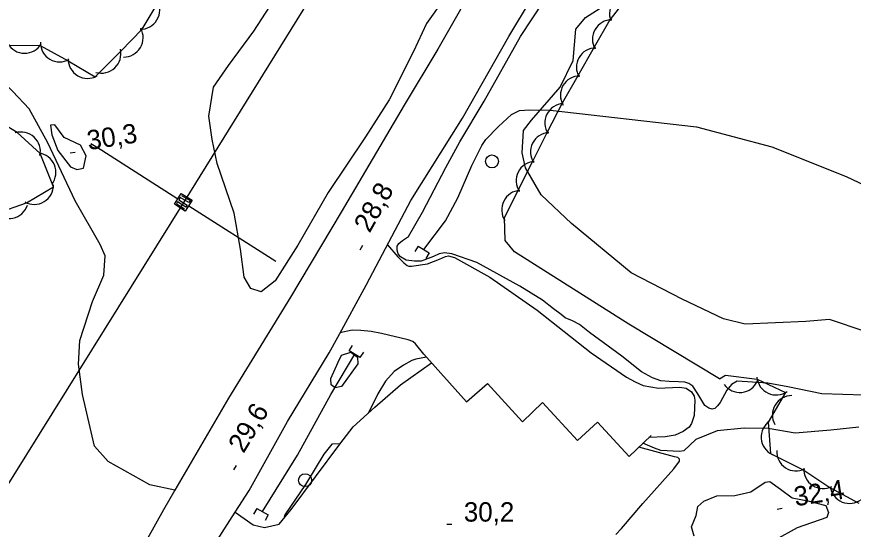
# Model space of a CAD drawing. Extents: x 646142 to 649934, y 5874075 to 5876351.
# Drawn here: x 648161.2 to 648290.8, y 5875445.6 to 5875524.9 of the extents above; entities that cross this region are included whole.
import ezdxf

# ---------------------------------------------------------------- set-up
doc = ezdxf.new("R2010")
doc.units = 0
for name, color, linetype in [('Niveau 1', 7, 'Continuous'), ('Niveau 19', 7, 'Continuous'), ('Niveau 2', 7, 'Continuous'), ('Niveau 21', 7, 'Continuous'), ('Niveau 22', 7, 'Continuous'), ('Niveau 26', 7, 'Continuous'), ('Niveau 3', 7, 'Continuous'), ('Niveau 36', 7, 'Continuous'), ('Niveau 37', 7, 'Continuous'), ('Niveau 4', 7, 'Continuous'), ('Niveau 44', 7, 'Continuous')]:
    doc.layers.add(name, color=color, linetype=linetype)

msp = doc.modelspace()

# ---------------------------------------------------------------- linework, layer by layer
at = {"layer": 'Niveau 1'}
for points in [[(648171.58, 5875501.45), (648172.01, 5875503.38), (648171.14, 5875505.04), (648168.58, 5875506.22), (648167.17, 5875508.17), (648166.49, 5875508.12), (648166.66, 5875506.64), (648167.59, 5875504.18), (648169.56, 5875501.69), (648170.56, 5875501.26), (648171.58, 5875501.45)], [(648224.69, 5875472.21), (648223.04, 5875471.91), (648222.42, 5875471.68), (648221.14, 5875470.99), (648219.67, 5875469.97), (648218.33, 5875468.52), (648217.17, 5875466.55), (648215.68, 5875463.51)], [(648291.63, 5875461.36), (648287.32, 5875460.9), (648281.8, 5875460.46), (648277.63, 5875461.15), (648273.91, 5875461.2), (648269.7, 5875460.8), (648266.43, 5875459.45), (648264.56, 5875457.69), (648263.9, 5875457.63)], [(648211.31, 5875458.79), (648210.02, 5875458.75), (648208.81, 5875457.22), (648205.96, 5875452.5), (648202.76, 5875447.82), (648202.6, 5875447.26)], [(648263.9, 5875457.63), (648261.01, 5875457.78), (648259.99, 5875458.12), (648258.21, 5875458.88)]]:
    msp.add_lwpolyline(points, dxfattribs=at)
at = {"layer": 'Niveau 19'}
for points in [[(648218.66, 5875489.6), (648220.25, 5875487.76), (648221.18, 5875486.8), (648221.73, 5875486.37), (648221.95, 5875486.31), (648222.39, 5875486.29), (648224.86, 5875486.63), (648226.71, 5875487.39), (648227.65, 5875487.78), (648228.12, 5875487.87), (648229.05, 5875487.61), (648234.53, 5875484.58), (648241.81, 5875479.48), (648250.2, 5875472.9), (648255.66, 5875469.11), (648257, 5875468.38), (648258.25, 5875467.82), (648260.62, 5875467.4), (648261.64, 5875467.44), (648263.92, 5875467.58), (648264.89, 5875467.4), (648265.72, 5875466.84), (648266.14, 5875466.18), (648266.24, 5875465.54), (648266.14, 5875463.19), (648265.75, 5875461.93), (648265.39, 5875461.38), (648264.45, 5875460.73), (648263.19, 5875460.14), (648261.64, 5875459.88), (648259.13, 5875459.77)], [(648224.29, 5875472.66), (648223.02, 5875474.25), (648222.56, 5875474.65), (648221.84, 5875474.87), (648217.72, 5875475.87), (648216.13, 5875476.18), (648214.52, 5875476.34), (648213.18, 5875476.39), (648211.3, 5875475.97)], [(648203.73, 5875448.65), (648211.28, 5875458.75), (648213.36, 5875461.41), (648216.71, 5875464.45), (648220.68, 5875467.91), (648225.46, 5875471.35)], [(648254.02, 5875444.78), (648254.92, 5875445.69), (648258.19, 5875449.56), (648262.98, 5875454.95), (648263.86, 5875456.11), (648263.88, 5875456.43), (648263.61, 5875456.66), (648263.12, 5875456.79), (648257.59, 5875458.28)], [(648195.09, 5875448.23), (648197.88, 5875446.27), (648199.63, 5875445.84), (648201.88, 5875446.37), (648203.73, 5875448.65)]]:
    msp.add_lwpolyline(points, dxfattribs=at)
at = {"layer": 'Niveau 2'}
for points in [[(648221.92, 5875490.9), (648224.08, 5875494.66), (648227.69, 5875501.57), (648229.86, 5875505.55), (648233.63, 5875511.83), (648239.24, 5875521.84), (648242.85, 5875527.3), (648247.43, 5875535.04), (648249.72, 5875537.29), (648251.34, 5875537.94), (648254.28, 5875537.77), (648256.44, 5875537.94), (648258.1, 5875538.71), (648263.71, 5875539.61), (648267.19, 5875539.89), (648270.67, 5875540.92), (648272.58, 5875543.72), (648273.88, 5875546.24), (648277.07, 5875547.99), (648281.37, 5875550.29), (648285.25, 5875552.78)], [(648227.65, 5875528.03), (648224.7, 5875523.83), (648222.67, 5875519.52), (648218.93, 5875512.03), (648215.23, 5875506.32), (648209.45, 5875497.68), (648204.78, 5875489.53), (648201.24, 5875484.01), (648199.12, 5875482.34), (648197.48, 5875482.85), (648196.48, 5875484.61), (648195.87, 5875488.94), (648194.93, 5875494.5), (648192.29, 5875502.18), (648191.49, 5875505.92), (648190.99, 5875509.5), (648191.74, 5875514), (648194.02, 5875517.35), (648197.98, 5875522.67), (648200.45, 5875526.5)], [(648274.06, 5875477.34), (648270.67, 5875478.16), (648264.3, 5875481.16), (648256.41, 5875485.25), (648247.17, 5875492.87), (648242.47, 5875497.33), (648240.03, 5875501.52), (648239.51, 5875503.84), (648239.71, 5875507.31), (648240.96, 5875508.91), (648245.41, 5875513.99), (648247.39, 5875518.13), (648247.84, 5875522.95), (648249.3, 5875524.8), (648252.16, 5875526.58)], [(648272.79, 5875468.47), (648271.94, 5875468), (648271.23, 5875467.12), (648270.18, 5875465.19), (648269.77, 5875464.66), (648269.33, 5875464.26), (648268.94, 5875464.18), (648268.43, 5875464.31), (648267.78, 5875464.74), (648266.7, 5875466.51), (648265.95, 5875467.7), (648265.31, 5875468.15), (648264.68, 5875468.32), (648263.7, 5875468.39), (648262.3, 5875468.42), (648261, 5875468.56), (648259.69, 5875469.03), (648257.97, 5875469.94), (648254.93, 5875472.38), (648249.96, 5875476.04), (648248.37, 5875477.28), (648247.29, 5875477.84), (648246.19, 5875478.29), (648245.56, 5875478.83), (648244.39, 5875479.68), (648242.66, 5875481.01), (648239.17, 5875483.18), (648232.47, 5875486.87), (648228.6, 5875488.19), (648227.47, 5875488.33), (648226.66, 5875488.2), (648225.79, 5875487.8), (648223.87, 5875487.07), (648222.83, 5875487.06), (648221.56, 5875487.21), (648220.69, 5875487.75), (648220.29, 5875488.22), (648220.16, 5875488.77), (648220.17, 5875489.37), (648220.4, 5875489.79), (648220.98, 5875490.26), (648221.92, 5875490.9)], [(648292.63, 5875476.18), (648287.09, 5875478.04), (648283.44, 5875477.74), (648274.06, 5875477.34)], [(648211.52, 5875472.51), (648212.98, 5875472.98), (648214.02, 5875472.2), (648214.09, 5875471.17), (648211.52, 5875467.65), (648210.56, 5875467.46), (648209.95, 5875467.95), (648209.9, 5875468.9), (648211, 5875471.46), (648211.52, 5875472.51)], [(648329.33, 5875422.84), (648327.76, 5875428.25), (648327.16, 5875436.24), (648326.49, 5875439.81), (648324.68, 5875443.29), (648321.81, 5875445.76), (648320.65, 5875448.94), (648318.4, 5875450.77), (648314.82, 5875451.86), (648310.39, 5875452.19), (648308.79, 5875453.62), (648306.98, 5875457.09), (648303.94, 5875462.6), (648300.97, 5875465.52), (648297.95, 5875466.08), (648292.43, 5875466.33), (648285.94, 5875466.55), (648280.64, 5875467.62), (648277.56, 5875468.18), (648272.79, 5875468.47)], [(648266.13, 5875444.51), (648265.74, 5875445.94), (648266.46, 5875447.72), (648266.73, 5875449.09), (648267.67, 5875449.94), (648269.66, 5875450.76), (648272.46, 5875450.82), (648274.9, 5875451.39), (648277.13, 5875452.88), (648277.84, 5875452.97), (648279.5, 5875451.79), (648281.34, 5875450.44), (648283.75, 5875449.95), (648286.54, 5875449.26), (648286.97, 5875448.15), (648286.68, 5875447.38), (648282.12, 5875445.81), (648278.72, 5875443.93)]]:
    msp.add_lwpolyline(points, dxfattribs=at)
at = {"layer": 'Niveau 21'}
for points in [[(648156.25, 5875385.1), (648164.35, 5875397.84), (648173.2, 5875412.81), (648180.57, 5875424.68), (648186.35, 5875434.69), (648189.37, 5875439.36), (648195.09, 5875448.23), (648197.23, 5875451.55), (648203.19, 5875462.26), (648209.61, 5875472.9), (648210.95, 5875475.33), (648215.36, 5875483.37), (648215.93, 5875484.44), (648222.29, 5875496.47), (648230.28, 5875509.19), (648237.47, 5875521.85), (648244.6, 5875533.81)], [(648233.33, 5875531.95), (648226.44, 5875519.89), (648221.24, 5875511.19), (648211.48, 5875494.64), (648203.63, 5875481.47), (648194.03, 5875465.86), (648185.72, 5875451.61), (648183.97, 5875448.6), (648179.02, 5875439.69), (648176.6, 5875435.35), (648175.37, 5875434.91), (648172.87, 5875434.59), (648168.31, 5875434.22), (648165.77, 5875434.36), (648162, 5875435.67), (648157.63, 5875437.39)]]:
    msp.add_lwpolyline(points, dxfattribs=at)
at = {"layer": 'Niveau 22'}
msp.add_lwpolyline([(648185.72, 5875451.61), (648181.87, 5875452.45), (648175.41, 5875456.07), (648173.28, 5875458.42), (648171.41, 5875466.44), (648170.83, 5875471.11), (648171.01, 5875474.8), (648172.97, 5875480.83), (648174.73, 5875484.88), (648174.96, 5875487.89), (648174.14, 5875489.66), (648170.3, 5875496.38), (648166.07, 5875505.36), (648163.15, 5875510.65), (648160.65, 5875513.32), (648156.2, 5875517.57)], dxfattribs=at)
at = {"layer": 'Niveau 26'}
for p, q in [((648223.41, 5875489.39), (648222.89, 5875488.54)), ((648223.41, 5875489.39), (648225.13, 5875488.34)), ((648225.13, 5875488.34), (648224.61, 5875487.48)), ((648212.73, 5875473.19), (648213.25, 5875474.04)), ((648214.45, 5875472.14), (648212.73, 5875473.19)), ((648214.45, 5875472.14), (648214.97, 5875472.99)), ((648198.43, 5875448.8), (648197.93, 5875447.93)), ((648198.43, 5875448.8), (648200.18, 5875447.8)), ((648200.18, 5875447.8), (648199.69, 5875446.93))]:
    msp.add_line(p, q, dxfattribs=at)
at = {"layer": 'Niveau 3'}
for p, q in [((648169.52, 5875503.84), (648170.31, 5875503.96)), ((648214.44, 5875488.82), (648214.83, 5875489.52)), ((648194.85, 5875454.76), (648195.26, 5875455.45)), ((648279, 5875448.71), (648279.79, 5875448.84)), ((648227.84, 5875446.34), (648228.64, 5875446.34))]:
    msp.add_line(p, q, dxfattribs=at)
at = {"layer": 'Niveau 36'}
for p, q in [((648172.74, 5875505.27), (648174.4, 5875504.22)), ((648174.4, 5875504.22), (648186.19, 5875496.71)), ((648187.88, 5875495.64), (648201.35, 5875487.08))]:
    msp.add_line(p, q, dxfattribs=at)
for points in [[(648600.59, 5876162.13), (648551.33, 5876082.95), (648424.31, 5875879.18), (648303.24, 5875683.36), (648187.06, 5875496.14), (648107.92, 5875369.28), (648085.7, 5875326.63)], [(648186.74, 5875497.24), (648188.1, 5875496.43), (648187.9, 5875496.12), (648186.57, 5875496.9), (648186.37, 5875496.58), (648187.64, 5875495.75), (648187.45, 5875495.44), (648186.15, 5875496.24), (648185.97, 5875495.96), (648187.21, 5875495.14)]]:
    msp.add_lwpolyline(points, dxfattribs=at)
msp.add_lwpolyline([(648185.66, 5875495.87), (648186.73, 5875497.56), (648188.42, 5875496.49), (648187.34, 5875494.8)], close=True, dxfattribs=at)
for centre in [(648234.84, 5875502.5), (648205.9, 5875453.17)]:
    msp.add_circle(centre, 1, dxfattribs=at)
at = {"layer": 'Niveau 37'}
msp.add_lwpolyline([(648224.29, 5875472.66), (648230.89, 5875465.31), (648234.14, 5875468.14), (648239.58, 5875462.2), (648242.64, 5875465.2), (648248.08, 5875459.3), (648251.18, 5875462.17), (648256.1, 5875456.83), (648259.48, 5875460.1)], dxfattribs=at)
at = {"layer": 'Niveau 4'}
for points in [[(648224.27, 5875488.86), (648227.63, 5875493.32), (648229.54, 5875496.89), (648231.74, 5875501.89), (648233.25, 5875504.95), (648233.91, 5875505.89), (648235.84, 5875507.89), (648237.87, 5875509.76), (648239.1, 5875510.38), (648240.67, 5875510.47), (648243.84, 5875510.45), (648266.51, 5875507.83), (648278.2, 5875504.78), (648289.69, 5875500.17), (648302.31, 5875494.16)], [(648199.3, 5875448.3), (648204.7, 5875457.02), (648209.87, 5875466.43), (648213.6, 5875472.66)]]:
    msp.add_lwpolyline(points, dxfattribs=at)
at = {"layer": 'Niveau 44'}
for points in [[(648264.4, 5875534.25), (648259.27, 5875532.3), (648256.26, 5875528.5), (648253.08, 5875524.41), (648250.67, 5875520.19), (648248.11, 5875515.73), (648245.7, 5875511.51), (648243.31, 5875506.94), (648241.15, 5875502.6), (648238.85, 5875497.99), (648236.76, 5875493.81)], [(648173.4, 5875515.6), (648177.34, 5875519.54), (648180.66, 5875522.95), (648183.15, 5875527.12)], [(648160.02, 5875520.5), (648164.87, 5875520.44), (648169.23, 5875518.07), (648173.4, 5875515.6)], [(648158.02, 5875494.43), (648162.76, 5875496.08), (648166.93, 5875498.58), (648164.89, 5875503.71), (648161.31, 5875506.99), (648156.83, 5875509.66)], [(648270.08, 5875468.84), (648256.03, 5875477.3), (648238.33, 5875488.49), (648236.86, 5875490.28), (648236.76, 5875493.81)], [(648270.08, 5875468.84), (648270.98, 5875469.44), (648275.91, 5875468.79), (648280.31, 5875466.74), (648277.59, 5875462.14), (648277.95, 5875457.29), (648283.11, 5875454.72), (648287.18, 5875452.06), (648291.65, 5875449.64)]]:
    msp.add_lwpolyline(points, dxfattribs=at)
for centre, start, end in [((648256.04, 5875525.39), 81.5817, 201.5596), ((648180.39, 5875525.94), 269.1403, 29.1182), ((648253.4, 5875521.42), 90.2619, 210.2399), ((648177.82, 5875521.65), 269.1403, 29.1182), ((648162.47, 5875522.24), 209.2574, 329.2354), ((648167.91, 5875520.9), 179.3707, 299.3486), ((648174.37, 5875519.16), 253.3673, 13.3452), ((648250.92, 5875517.08), 90.2619, 210.2399), ((648172.21, 5875518.35), 179.3707, 299.3486), ((648248.44, 5875512.74), 90.2619, 210.2399), ((648246.04, 5875508.46), 93.5083, 213.4863), ((648161.91, 5875504.05), 347.4409, 107.4188), ((648243.81, 5875503.98), 93.5083, 213.4863), ((648164.32, 5875500.81), 322.7234, 82.7014), ((648241.57, 5875499.51), 93.5083, 213.4863), ((648163.94, 5875498.85), 240.9851, 0.963), ((648239.34, 5875495.03), 93.5083, 213.4863), ((648160.04, 5875496.65), 221.91, 341.8879), ((648273.22, 5875469.75), 215.9321, 335.9101), ((648278.85, 5875469.36), 184.9957, 304.9736), ((648281.26, 5875463.26), 89.5063, 209.4843), ((648279.53, 5875459.85), 124.314, 244.292), ((648281.92, 5875457.6), 176.8915, 296.8694), ((648286.11, 5875454.87), 176.8915, 296.8694), ((648290.2, 5875452.57), 187.9317, 307.9097)]:
    msp.add_arc(centre, 3, start, end, dxfattribs=at)

# ---------------------------------------------------------------- texts
at = {"layer": 'Niveau 3'}
for s, rotation, p in [('30,3 ', 8.9405, (648172.37, 5875504.25)), ('28,8 ', 60.6347, (648215.89, 5875491.31)), ('29,6 ', 58.983, (648196.37, 5875457.21)), ('32,4 ', 8.9405, (648281.85, 5875449.12))]:
    msp.add_text(s, height=3, rotation=rotation, dxfattribs=at).set_placement(p)
msp.add_text('30,2 ', height=3, dxfattribs=at).set_placement((648230.48, 5875446.76))

doc.saveas('drawing.dxf')
